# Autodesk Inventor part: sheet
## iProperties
Created: 2007-11
Part Number: sheet
Document SubType Name: Modeling
Designer: Administrateur
Author: Administrateur
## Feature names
1. Extrusion1
2. Extrusion3
3. Hole2
